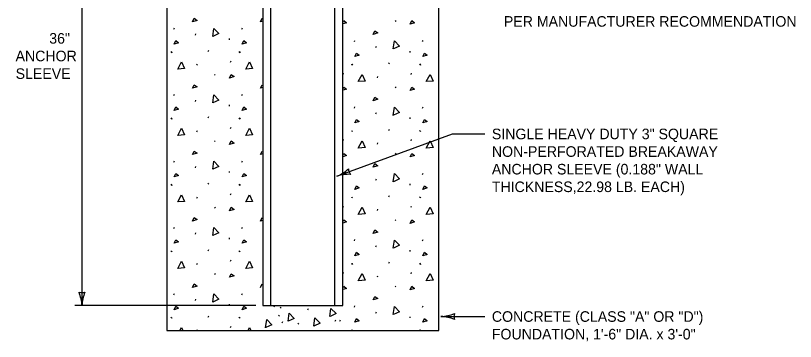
# Model space of a CAD drawing. Extents: x 49940 to 50043, y 49986 to 50011.
# Drawn here: x 49951.034 to 49955.464, y 49992.508 to 49994.357 of the extents above; entities that cross this region are included whole.
import ezdxf

# ---------------------------------------------------------------- set-up
doc = ezdxf.new("R2010")
doc.units = 0
for name, color, linetype in [('Level 1', 7, 'Continuous'), ('Level 2', 7, 'Continuous'), ('Level 3', 7, 'Continuous'), ('Level 4', 7, 'Continuous')]:
    doc.layers.add(name, color=color, linetype=linetype)

msp = doc.modelspace()

# ---------------------------------------------------------------- linework, layer by layer
at = {"layer": 'Level 1'}
for p, q in [((49951.8937, 49995.2968), (49951.8937, 49992.5705)), ((49953.4386, 49992.5705), (49953.4386, 49995.2968)), ((49953.1906, 49994.3298), (49953.1937, 49994.3248)), ((49951.933, 49994.2804), (49951.9362, 49994.2876)), ((49952.3195, 49994.2804), (49952.3228, 49994.2876)), ((49952.0557, 49994.2472), (49952.0588, 49994.2545)), ((49952.2475, 49994.2271), (49952.2482, 49994.2197)), ((49952.959, 49994.2095), (49952.9622, 49994.2168)), ((49953.0816, 49994.1764), (49953.0847, 49994.1837)), ((49953.3455, 49994.2095), (49953.3488, 49994.2168)), ((49951.916, 49994.1536), (49951.9193, 49994.1489)), ((49951.9193, 49994.1518), (49951.9226, 49994.147)), ((49952.129, 49994.1536), (49952.1323, 49994.1609)), ((49952.3025, 49994.1536), (49952.3059, 49994.1489)), ((49952.3059, 49994.1518), (49952.3091, 49994.147)), ((49953.2735, 49994.1561), (49953.2742, 49994.1489)), ((49952.2549, 49994.0939), (49952.2582, 49994.1011)), ((49952.0637, 49994.0753), (49952.067, 49994.0825)), ((49952.942, 49994.0828), (49952.9452, 49994.078)), ((49952.9452, 49994.081), (49952.9484, 49994.0762)), ((49953.155, 49994.0828), (49953.1583, 49994.0902)), ((49953.3285, 49994.0828), (49953.3317, 49994.078)), ((49953.3317, 49994.081), (49953.335, 49994.0762)), ((49952.1647, 49994.0237), (49952.1679, 49994.0187)), ((49952.8945, 49994.023), (49952.8975, 49994.0302)), ((49953.0897, 49994.0044), (49953.0928, 49994.0117)), ((49953.2808, 49994.023), (49953.2841, 49994.0302)), ((49953.1906, 49993.9528), (49953.1937, 49993.9479)), ((49951.933, 49993.9034), (49951.9362, 49993.9107)), ((49952.0557, 49993.8703), (49952.0588, 49993.8776)), ((49952.3195, 49993.9034), (49952.3228, 49993.9107)), ((49952.2475, 49993.8501), (49952.2482, 49993.8428)), ((49952.959, 49993.8324), (49952.9622, 49993.8398)), ((49953.3455, 49993.8324), (49953.3488, 49993.8398)), ((49953.0816, 49993.7994), (49953.0847, 49993.8067)), ((49951.916, 49993.7768), (49951.9193, 49993.772)), ((49951.9193, 49993.7749), (49951.9226, 49993.7702)), ((49952.129, 49993.7768), (49952.1323, 49993.784)), ((49952.3025, 49993.7768), (49952.3059, 49993.772)), ((49952.3059, 49993.7749), (49952.3091, 49993.7702)), ((49953.2735, 49993.7792), (49953.2742, 49993.772)), ((49952.0637, 49993.6984), (49952.067, 49993.7056)), ((49952.2549, 49993.7169), (49952.2582, 49993.7242)), ((49952.942, 49993.7058), (49952.9452, 49993.7008)), ((49952.9452, 49993.704), (49952.9484, 49993.6991)), ((49953.155, 49993.7058), (49953.1583, 49993.7131)), ((49953.3285, 49993.7058), (49953.3317, 49993.7008)), ((49953.3317, 49993.704), (49953.335, 49993.6991)), ((49952.8945, 49993.646), (49952.8975, 49993.6532)), ((49953.2808, 49993.646), (49953.2841, 49993.6532)), ((49952.1647, 49993.6468), (49952.1679, 49993.6419)), ((49953.0897, 49993.6274), (49953.0928, 49993.6347)), ((49953.1906, 49993.5757), (49953.1937, 49993.5709)), ((49951.933, 49993.5263), (49951.9362, 49993.5337)), ((49952.3195, 49993.5263), (49952.3228, 49993.5337)), ((49952.0557, 49993.4934), (49952.0588, 49993.5007)), ((49952.2475, 49993.4731), (49952.2482, 49993.466)), ((49953.3455, 49993.4556), (49953.3488, 49993.4628)), ((49951.916, 49993.3997), (49951.9193, 49993.3949)), ((49951.9193, 49993.3979), (49951.9226, 49993.393)), ((49952.129, 49993.3997), (49952.1323, 49993.407)), ((49952.3025, 49993.3997), (49952.3059, 49993.3949)), ((49952.3059, 49993.3979), (49952.3091, 49993.393)), ((49953.0816, 49993.4225), (49953.0847, 49993.4299)), ((49953.2735, 49993.4022), (49953.2742, 49993.3949)), ((49952.2549, 49993.34), (49952.2582, 49993.3472)), ((49952.0637, 49993.3213), (49952.067, 49993.3286)), ((49952.942, 49993.329), (49952.9452, 49993.3239)), ((49952.9452, 49993.3269), (49952.9484, 49993.3221)), ((49953.155, 49993.329), (49953.1583, 49993.3362)), ((49953.3285, 49993.329), (49953.3317, 49993.3239)), ((49953.3317, 49993.3269), (49953.335, 49993.3221)), ((49952.1647, 49993.2698), (49952.1679, 49993.2649)), ((49952.8945, 49993.269), (49952.8975, 49993.2763)), ((49953.0897, 49993.2505), (49953.0928, 49993.2577)), ((49953.2808, 49993.269), (49953.2841, 49993.2763)), ((49953.1906, 49993.1987), (49953.1937, 49993.194)), ((49951.933, 49993.1495), (49951.9362, 49993.1568)), ((49952.0557, 49993.1164), (49952.0588, 49993.1237)), ((49952.3195, 49993.1495), (49952.3228, 49993.1568)), ((49952.2475, 49993.0961), (49952.2482, 49993.0888)), ((49952.959, 49993.0786), (49952.9622, 49993.0859)), ((49953.3455, 49993.0786), (49953.3488, 49993.0859)), ((49953.0816, 49993.0456), (49953.0847, 49993.0528)), ((49951.916, 49993.0228), (49951.9193, 49993.018)), ((49951.9193, 49993.021), (49951.9226, 49993.016)), ((49952.129, 49993.0228), (49952.1323, 49993.0301)), ((49952.3025, 49993.0228), (49952.3059, 49993.018)), ((49952.3059, 49993.021), (49952.3091, 49993.016)), ((49953.2735, 49993.0251), (49953.2742, 49993.0181)), ((49952.0637, 49992.9444), (49952.067, 49992.9517)), ((49952.2549, 49992.9629), (49952.2582, 49992.9702)), ((49952.942, 49992.9519), (49952.9452, 49992.947)), ((49952.9452, 49992.9501), (49952.9484, 49992.9451)), ((49953.155, 49992.9519), (49953.1583, 49992.9592)), ((49953.3285, 49992.9519), (49953.3317, 49992.947)), ((49953.3317, 49992.9501), (49953.335, 49992.9451)), ((49952.8945, 49992.8919), (49952.8975, 49992.8994)), ((49953.2808, 49992.8919), (49953.2841, 49992.8994)), ((49952.1647, 49992.8928), (49952.1679, 49992.888)), ((49953.0897, 49992.8735), (49953.0928, 49992.8807)), ((49953.1906, 49992.8219), (49953.1937, 49992.817)), ((49951.933, 49992.7725), (49951.9362, 49992.7797)), ((49952.3195, 49992.7725), (49952.3228, 49992.7797)), ((49952.0557, 49992.7395), (49952.0588, 49992.7467)), ((49952.2475, 49992.7191), (49952.2482, 49992.7119)), ((49952.439, 49992.7115), (49952.8933, 49992.7115)), ((49952.503, 49992.7049), (49952.5061, 49992.712)), ((49952.5394, 49992.6957), (49952.5427, 49992.7029)), ((49952.6944, 49992.6866), (49952.6976, 49992.6938)), ((49952.959, 49992.7016), (49952.9622, 49992.7088)), ((49953.3455, 49992.7016), (49953.3488, 49992.7088)), ((49951.916, 49992.6458), (49951.9193, 49992.641)), ((49951.9193, 49992.644), (49951.9226, 49992.6391)), ((49952.129, 49992.6458), (49952.1323, 49992.6531)), ((49952.3025, 49992.6458), (49952.3059, 49992.641)), ((49952.3059, 49992.644), (49952.3091, 49992.6391)), ((49952.5304, 49992.6503), (49952.5336, 49992.6575)), ((49953.0816, 49992.6686), (49953.0847, 49992.6758)), ((49953.2735, 49992.6482), (49953.2742, 49992.641)), ((49952.2549, 49992.5859), (49952.2582, 49992.5934)), ((49952.5486, 49992.6139), (49952.5518, 49992.6211)), ((49952.6398, 49992.6048), (49952.643, 49992.6121)), ((49952.8497, 49992.6231), (49952.8528, 49992.6302)), ((49952.8769, 49992.6231), (49952.8802, 49992.6302)), ((49951.8937, 49992.5705), (49953.4386, 49992.5705)), ((49952.065, 49992.5705), (49952.067, 49992.5748)), ((49952.942, 49992.575), (49952.945, 49992.5705)), ((49952.9452, 49992.5732), (49952.9469, 49992.5705)), ((49953.3285, 49992.575), (49953.3315, 49992.5705)), ((49953.3317, 49992.5732), (49953.3334, 49992.5705))]:
    msp.add_line(p, q, dxfattribs=at)
for points in [[(49952.8933, 49992.7115), (49952.8933, 49995.5448), (49952.439, 49995.5448), (49952.439, 49992.7115)], [(49952.0396, 49994.3219), (49952.0494, 49994.3422), (49952.0655, 49994.33), (49952.0396, 49994.3219)], [(49952.4263, 49994.3219), (49952.4359, 49994.3422), (49952.439, 49994.3399)], [(49952.439, 49994.326), (49952.4263, 49994.3219)], [(49952.8933, 49994.3186), (49952.8983, 49994.329), (49952.9145, 49994.3168), (49952.8933, 49994.3102)], [(49953.2753, 49994.3087), (49953.2849, 49994.329), (49953.3011, 49994.3168), (49953.2753, 49994.3087)], [(49952.1538, 49994.239), (49952.1603, 49994.285), (49952.1891, 49994.2552), (49952.1546, 49994.2392)], [(49953.0656, 49994.2511), (49953.0753, 49994.2714), (49953.0914, 49994.2591), (49953.0656, 49994.2511)], [(49951.9346, 49994.1956), (49951.9443, 49994.2157), (49951.9604, 49994.2037), (49951.9346, 49994.1956)], [(49952.3212, 49994.1956), (49952.331, 49994.2157), (49952.3469, 49994.2037), (49952.3212, 49994.1956)], [(49953.1798, 49994.168), (49953.1862, 49994.214), (49953.2151, 49994.1843), (49953.1807, 49994.1683)], [(49952.9605, 49994.1247), (49952.9701, 49994.1449), (49952.9864, 49994.1328), (49952.9605, 49994.1247)], [(49953.3471, 49994.1247), (49953.3568, 49994.1449), (49953.3729, 49994.1328), (49953.3471, 49994.1247)], [(49951.9549, 49994.0536), (49951.9766, 49994.0947), (49951.9936, 49994.0568), (49951.9556, 49994.0536)], [(49952.3413, 49994.0536), (49952.3632, 49994.0947), (49952.38, 49994.0568), (49952.3421, 49994.0536)], [(49952.2493, 49994.0026), (49952.259, 49994.0229), (49952.2751, 49994.0108), (49952.2493, 49994.0026)], [(49952.9807, 49993.9826), (49953.0025, 49994.0238), (49953.0194, 49993.9859), (49952.9814, 49993.9826)], [(49953.3673, 49993.9826), (49953.3891, 49994.0238), (49953.406, 49993.9859), (49953.3681, 49993.9826)], [(49952.0396, 49993.945), (49952.0494, 49993.9652), (49952.0655, 49993.9531), (49952.0396, 49993.945)], [(49952.4263, 49993.945), (49952.4359, 49993.9652), (49952.439, 49993.9628)], [(49952.439, 49993.949), (49952.4263, 49993.945)], [(49952.8933, 49993.9416), (49952.8983, 49993.952), (49952.9145, 49993.9398), (49952.8933, 49993.9332)], [(49953.2753, 49993.9318), (49953.2849, 49993.952), (49953.3011, 49993.9398), (49953.2753, 49993.9318)], [(49952.1538, 49993.862), (49952.1603, 49993.9081), (49952.1891, 49993.8783), (49952.1546, 49993.8623)], [(49953.0656, 49993.8741), (49953.0753, 49993.8943), (49953.0914, 49993.8822), (49953.0656, 49993.8741)], [(49951.9346, 49993.8187), (49951.9443, 49993.8388), (49951.9604, 49993.8269), (49951.9346, 49993.8187)], [(49952.3212, 49993.8187), (49952.331, 49993.8388), (49952.3469, 49993.8269), (49952.3212, 49993.8187)], [(49953.1798, 49993.7911), (49953.1862, 49993.8373), (49953.2151, 49993.8075), (49953.1807, 49993.7914)], [(49952.9605, 49993.7478), (49952.9701, 49993.768), (49952.9864, 49993.7558), (49952.9605, 49993.7478)], [(49953.3471, 49993.7478), (49953.3568, 49993.768), (49953.3729, 49993.7558), (49953.3471, 49993.7478)], [(49951.9549, 49993.6766), (49951.9766, 49993.7177), (49951.9936, 49993.6799), (49951.9556, 49993.6766)], [(49952.3413, 49993.6766), (49952.3632, 49993.7177), (49952.38, 49993.6799), (49952.3421, 49993.6766)], [(49952.2493, 49993.6256), (49952.259, 49993.6459), (49952.2751, 49993.6338), (49952.2493, 49993.6256)], [(49952.9807, 49993.6056), (49953.0025, 49993.6468), (49953.0194, 49993.6089), (49952.9814, 49993.6056)], [(49953.3673, 49993.6056), (49953.3891, 49993.6468), (49953.406, 49993.6089), (49953.3681, 49993.6056)], [(49952.0396, 49993.568), (49952.0494, 49993.5882), (49952.0655, 49993.5761), (49952.0396, 49993.568)], [(49952.4263, 49993.568), (49952.4359, 49993.5882), (49952.439, 49993.5859)], [(49952.439, 49993.5721), (49952.4263, 49993.568)], [(49952.8933, 49993.5645), (49952.8983, 49993.575), (49952.9145, 49993.5629), (49952.8933, 49993.5562)], [(49953.2753, 49993.5548), (49953.2849, 49993.575), (49953.3011, 49993.5629), (49953.2753, 49993.5548)], [(49952.1538, 49993.4851), (49952.1603, 49993.5312), (49952.1891, 49993.5013), (49952.1546, 49993.4853)], [(49953.0656, 49993.4972), (49953.0753, 49993.5173), (49953.0914, 49993.5053), (49953.0656, 49993.4972)], [(49951.9346, 49993.4416), (49951.9443, 49993.4619), (49951.9604, 49993.4498), (49951.9346, 49993.4416)], [(49952.3212, 49993.4416), (49952.331, 49993.4619), (49952.3469, 49993.4498), (49952.3212, 49993.4416)], [(49953.1798, 49993.4142), (49953.1862, 49993.4603), (49953.2151, 49993.4304), (49953.1807, 49993.4144)], [(49952.9605, 49993.3708), (49952.9701, 49993.391), (49952.9864, 49993.3789), (49952.9605, 49993.3708)], [(49953.3471, 49993.3708), (49953.3568, 49993.391), (49953.3729, 49993.3789), (49953.3471, 49993.3708)], [(49951.9549, 49993.2996), (49951.9766, 49993.3408), (49951.9936, 49993.3028), (49951.9556, 49993.2996)], [(49952.3413, 49993.2996), (49952.3632, 49993.3408), (49952.38, 49993.3028), (49952.3421, 49993.2996)], [(49952.2493, 49993.2488), (49952.259, 49993.269), (49952.2751, 49993.2569), (49952.2493, 49993.2488)], [(49952.9807, 49993.2286), (49953.0025, 49993.2698), (49953.0194, 49993.232), (49952.9814, 49993.2286)], [(49953.3673, 49993.2286), (49953.3891, 49993.2698), (49953.406, 49993.232), (49953.3681, 49993.2286)], [(49952.0396, 49993.1911), (49952.0494, 49993.2112), (49952.0655, 49993.1992), (49952.0396, 49993.1911)], [(49952.4263, 49993.1911), (49952.4359, 49993.2112), (49952.439, 49993.209)], [(49952.439, 49993.195), (49952.4263, 49993.1911)], [(49952.8933, 49993.1876), (49952.8983, 49993.198), (49952.9145, 49993.1859), (49952.8933, 49993.1793)], [(49953.2753, 49993.1779), (49953.2849, 49993.198), (49953.3011, 49993.1859), (49953.2753, 49993.1779)], [(49952.1538, 49993.1081), (49952.1603, 49993.1543), (49952.1891, 49993.1243), (49952.1546, 49993.1084)], [(49953.0656, 49993.1202), (49953.0753, 49993.1404), (49953.0914, 49993.1282), (49953.0656, 49993.1202)], [(49951.9346, 49993.0647), (49951.9443, 49993.085), (49951.9604, 49993.0728), (49951.9346, 49993.0647)], [(49952.3212, 49993.0647), (49952.331, 49993.085), (49952.3469, 49993.0728), (49952.3212, 49993.0647)], [(49953.1798, 49993.0372), (49953.1862, 49993.0832), (49953.2151, 49993.0534), (49953.1807, 49993.0375)], [(49952.9605, 49992.9938), (49952.9701, 49993.0141), (49952.9864, 49993.0019), (49952.9605, 49992.9938)], [(49953.3471, 49992.9938), (49953.3568, 49993.0141), (49953.3729, 49993.0019), (49953.3471, 49992.9938)], [(49951.9549, 49992.9226), (49951.9766, 49992.9637), (49951.9936, 49992.9259), (49951.9556, 49992.9226)], [(49952.3413, 49992.9226), (49952.3632, 49992.9637), (49952.38, 49992.9259), (49952.3421, 49992.9226)], [(49952.2493, 49992.8719), (49952.259, 49992.8919), (49952.2751, 49992.8798), (49952.2493, 49992.8719)], [(49952.9807, 49992.8518), (49953.0025, 49992.8928), (49953.0194, 49992.855), (49952.9814, 49992.8518)], [(49953.3673, 49992.8518), (49953.3891, 49992.8928), (49953.406, 49992.855), (49953.3681, 49992.8518)], [(49952.0396, 49992.8141), (49952.0494, 49992.8342), (49952.0655, 49992.8221), (49952.0396, 49992.8141)], [(49952.4263, 49992.8141), (49952.4359, 49992.8342), (49952.439, 49992.8319)], [(49952.8933, 49992.8105), (49952.8983, 49992.8211), (49952.9145, 49992.809), (49952.8933, 49992.8024)], [(49953.2753, 49992.8009), (49953.2849, 49992.8211), (49953.3011, 49992.809), (49953.2753, 49992.8009)], [(49952.1538, 49992.7311), (49952.1603, 49992.7772), (49952.1891, 49992.7473), (49952.1546, 49992.7313)], [(49953.0656, 49992.7432), (49953.0753, 49992.7634), (49953.0914, 49992.7513), (49953.0656, 49992.7432)], [(49951.9346, 49992.6878), (49951.9443, 49992.708), (49951.9604, 49992.6959), (49951.9346, 49992.6878)], [(49952.3212, 49992.6878), (49952.331, 49992.708), (49952.3469, 49992.6959), (49952.3212, 49992.6878)], [(49952.8196, 49992.6494), (49952.8259, 49992.6955), (49952.8549, 49992.6657), (49952.8204, 49992.6496)], [(49953.1798, 49992.6602), (49953.1862, 49992.7064), (49953.2151, 49992.6765), (49953.1807, 49992.6605)], [(49952.5824, 49992.622), (49952.5888, 49992.6682), (49952.6177, 49992.6384), (49952.5832, 49992.6224)], [(49952.7283, 49992.5948), (49952.7348, 49992.6409), (49952.7637, 49992.6111), (49952.7291, 49992.5951)], [(49952.9605, 49992.617), (49952.9701, 49992.637), (49952.9864, 49992.6249), (49952.9605, 49992.617)], [(49953.3471, 49992.617), (49953.3568, 49992.637), (49953.3729, 49992.6249), (49953.3471, 49992.617)], [(49952.4547, 49992.5857), (49952.4612, 49992.6318), (49952.49, 49992.602), (49952.4556, 49992.5859)], [(49951.968, 49992.5705), (49951.9766, 49992.5868), (49951.9839, 49992.5705)], [(49952.3546, 49992.5705), (49952.3632, 49992.5868), (49952.3704, 49992.5705)]]:
    msp.add_lwpolyline(points, dxfattribs=at)
at = {"layer": 'Level 3'}
for p, q in [((49951.4113, 49995.5448), (49951.4113, 49992.7115)), ((49952.8597, 49993.4457), (49953.5154, 49993.6856)), ((49953.5154, 49993.6856), (49953.6999, 49993.6856)), ((49952.399, 49992.7115), (49951.3713, 49992.7115)), ((49953.4508, 49992.649), (49953.6999, 49992.649))]:
    msp.add_line(p, q, dxfattribs=at)
for centre, radius, start, end in [((49952.769, 49993.6603), 0.233, 292.9233, 312.1731), ((49952.9801, 49993.4898), 0.0548, 182.2348, 217.9572), ((49952.9274, 49993.234), 0.2223, 87.552, 107.7355), ((49951.4113, 49992.8397), 0.0548, 252.1388, 287.8612), ((49951.1786, 49992.7), 0.233, 2.8273, 22.0772), ((49951.6334, 49992.7024), 0.2223, 157.456, 177.6395), ((49953.4393, 49992.8817), 0.233, 272.8273, 292.0772), ((49953.4416, 49992.4269), 0.2223, 67.456, 87.6395), ((49953.579, 49992.649), 0.0548, 162.1388, 197.8612)]:
    msp.add_arc(centre, radius, start, end, dxfattribs=at)
at = {"layer": 'Level 4'}
for p, q in [((49952.4851, 49992.7115), (49952.4851, 49995.5448)), ((49952.8484, 49992.7115), (49952.8484, 49995.5448))]:
    msp.add_line(p, q, dxfattribs=at)

# ---------------------------------------------------------------- texts
at = {"layer": 'Level 2'}
for s, p in [('PER MANUFACTURER RECOMMENDATION', (49953.8083, 49994.2944)), ('36"', (49951.2253, 49994.1982)), ('ANCHOR', (49951.034, 49994.0982)), ('SLEEVE', (49951.0345, 49993.9982)), ('SINGLE HEAVY DUTY 3" SQUARE', (49953.7399, 49993.6556)), ('NON-PERFORATED BREAKAWAY', (49953.7399, 49993.5556)), ('ANCHOR SLEEVE (0.188" WALL ', (49953.7399, 49993.4556)), ('THICKNESS,22.98 LB. EACH)', (49953.7399, 49993.3556)), ('CONCRETE (CLASS "A" OR "D")', (49953.7399, 49992.619)), ('FOUNDATION, 1\'-6" DIA. x 3\'-0"', (49953.7399, 49992.519))]:
    msp.add_text(s, height=0.06, dxfattribs=at).set_placement(p)

doc.saveas('drawing.dxf')
